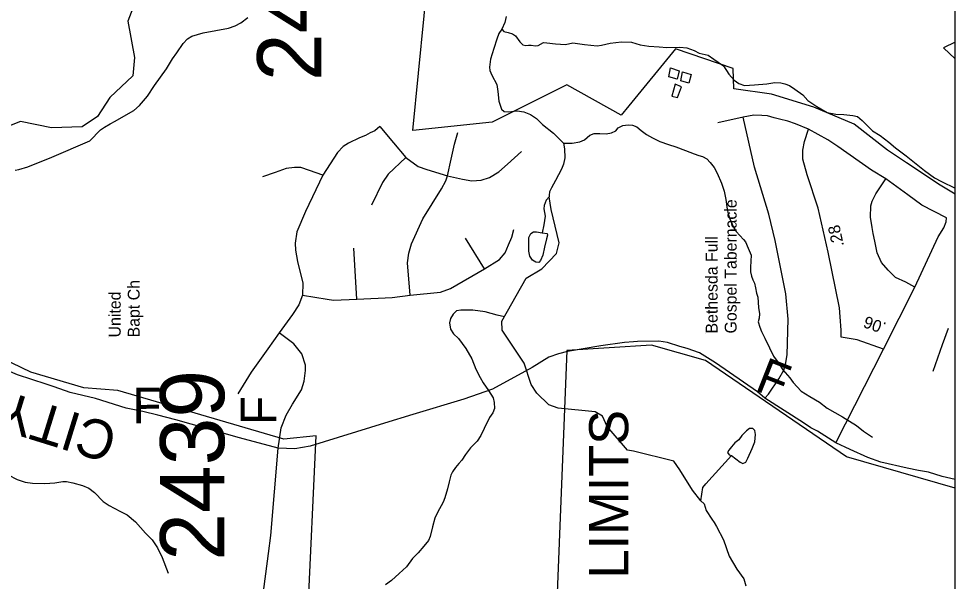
# Model space of a CAD drawing. Extents: x 1372027 to 1374286, y 553832 to 556743.
# Drawn here: x 1373346.9 to 1373483.1, y 554175.4 to 554256.9 of the extents above; entities that cross this region are included whole.
import ezdxf

# ---------------------------------------------------------------- set-up
doc = ezdxf.new("R2010")
doc.units = 0
for name, color, linetype in [('Old_Level_12', 7, 'Continuous'), ('Prop Dimension', 7, 'Continuous'), ('Prop Dimension Text', 7, 'Continuous'), ('Prop Guardrail', 7, 'Continuous'), ('Prop Paved Shoulder', 7, 'Continuous'), ('Sheet Clip Boundary CELL', 7, 'Continuous'), ('Sheet North Arrow Point CELL', 7, 'Continuous'), ('Sheet Sticker Preliminary CELL', 7, 'Continuous')]:
    doc.layers.add(name, color=color, linetype=linetype)

msp = doc.modelspace()

# ---------------------------------------------------------------- linework, layer by layer
at = {"layer": 'Prop Dimension'}
for points in [[(1373390.4, 554295.52), (1373383.17, 554280.73), (1373382.39, 554279.36), (1373381.04, 554279.17), (1373379.07, 554280.34), (1373376.02, 554281.86), (1373374.59, 554280.87), (1373372.97, 554278.37), (1373369.48, 554270.06), (1373367.31, 554268.19), (1373366.41, 554268.21), (1373364.1, 554266.68), (1373363.6, 554265.63), (1373363.97, 554260.02), (1373362.66, 554256.56), (1373363.65, 554251.29), (1373363.4, 554248.66), (1373360.07, 554245.52), (1373358.27, 554242.76), (1373356.06, 554241.27), (1373351.62, 554241.09), (1373347.13, 554242), (1373341.46, 554239.82)], [(1373417.56, 554257.23), (1373417.34, 554256.39), (1373416.94, 554255.43)], [(1373416.94, 554255.43), (1373416.49, 554254.81), (1373416.18, 554253.98), (1373415.78, 554252.6), (1373415.28, 554251.05), (1373415.14, 554249.88), (1373415.16, 554249.42), (1373415.49, 554248.74), (1373416.17, 554247.38), (1373416.36, 554246.37), (1373416.5, 554244.98), (1373416.7, 554244.26), (1373416.89, 554243.79), (1373417.26, 554243.45), (1373417.87, 554243.44), (1373419.16, 554243.58), (1373420.12, 554243.43), (1373421.08, 554243.03), (1373421.95, 554242.47), (1373422.83, 554241.61), (1373424.39, 554240.32), (1373425.88, 554238.9)], [(1373425.88, 554238.9), (1373426.03, 554238.06), (1373426.04, 554236.76), (1373425.85, 554235.83), (1373425.59, 554235.12), (1373424.72, 554233.46), (1373424.14, 554232.42), (1373423.84, 554231.8), (1373423.79, 554231.34), (1373423.79, 554231.08)], [(1373445.79, 554187), (1373444.57, 554188.56), (1373442.71, 554191.49), (1373441.87, 554192.75), (1373436, 554194.19), (1373435.16, 554194.37), (1373432.2, 554197.81), (1373431.54, 554199.31), (1373430.46, 554199.91), (1373425.08, 554200.45), (1373423.75, 554200.92), (1373422.01, 554202.6), (1373421.17, 554203.86), (1373420.15, 554206.97), (1373416.98, 554211.76), (1373416.93, 554213.07), (1373420.43, 554219.28), (1373422.73, 554220.65), (1373424.85, 554222.87), (1373425.22, 554224.45), (1373424.08, 554229.26), (1373423.79, 554231.08)], [(1373445.79, 554187), (1373446.25, 554186.58), (1373446.55, 554185.62), (1373447.39, 554184.37), (1373447.69, 554183.89), (1373448.05, 554183.29), (1373449.07, 554181.37), (1373449.9, 554178.98), (1373450.98, 554177.12), (1373452, 554175.68), (1373452.3, 554174.66)]]:
    msp.add_lwpolyline(points, dxfattribs=at)
at = {"layer": 'Prop Dimension Text'}
for points in [[(1373151.67, 554391.53), (1373151.67, 554060.53), (1373482.67, 554060.53), (1373482.67, 554391.53)], [(1373508.08, 554391.53), (1373508.08, 554060.53), (1373482.67, 554060.53), (1373482.67, 554391.53)]]:
    msp.add_lwpolyline(points, close=True, dxfattribs=at)
for points in [[(1373442.11, 554252.57), (1373435.36, 554244.29), (1373434.22, 554242.95), (1373426.33, 554247.36), (1373415.53, 554241.91), (1373404.03, 554240.74), (1373407.28, 554274.04)], [(1373482.67, 554253.55), (1373480.99, 554252.69), (1373482.67, 554251.13)], [(1373482.67, 554231.48), (1373480.47, 554232.77), (1373475.6, 554236.03), (1373472.84, 554237.87), (1373468, 554241.64), (1373462.19, 554244.11), (1373456.04, 554245.97), (1373450.58, 554246.78), (1373450.46, 554249.72), (1373442.11, 554252.57)], [(1373482.67, 554188.86), (1373466.92, 554193.38), (1373446.44, 554207.34), (1373438.62, 554209.57), (1373426.33, 554208.82), (1373424.84, 554171.24), (1373413.67, 554168.63), (1373414.42, 554122.11), (1373405.85, 554116.53), (1373395.43, 554113.92), (1373393.57, 554120.62), (1373386.65, 554120.29), (1373386.48, 554133.33), (1373386.62, 554163.49), (1373388.8, 554170.42), (1373390.01, 554196.42), (1373385.31, 554195.94), (1373361.22, 554203), (1373356.27, 554203.41), (1373348.59, 554205.69), (1373344.52, 554207.63)]]:
    msp.add_lwpolyline(points, dxfattribs=at)
at = {"layer": 'Prop Paved Shoulder'}
for p, q in [((1373451.93, 554242.66), (1373448.24, 554241.85)), ((1373414.42, 554220.65), (1373411.64, 554225.08)), ((1373395.9, 554216.25), (1373395.46, 554223.65)), ((1373472.25, 554209.02), (1373476.8, 554217.99)), ((1373465.36, 554195.41), (1373472.25, 554209.02))]:
    msp.add_line(p, q, dxfattribs=at)
for points in [[(1373346.34, 554234.97), (1373346.89, 554235.04), (1373348.19, 554235.46), (1373351.66, 554236.86), (1373357.14, 554239.21), (1373358.73, 554240.8), (1373359.28, 554241.21), (1373360.09, 554241.7), (1373360.86, 554242.06), (1373362.43, 554242.99), (1373363.55, 554243.61), (1373364.37, 554244.32), (1373365.51, 554245.69), (1373366.55, 554247.24), (1373368.28, 554249.68), (1373369.15, 554251.09), (1373369.8, 554252), (1373370.69, 554253.35), (1373371.33, 554254), (1373371.96, 554254.39), (1373373.6, 554254.88), (1373377.28, 554255.55), (1373378.23, 554255.91), (1373379.08, 554256.33), (1373380.1, 554257.11)], [(1373461.41, 554240.89), (1373459.52, 554241.67), (1373458.41, 554242.06), (1373457.18, 554242.35), (1373456.42, 554242.55), (1373455.47, 554242.84), (1373454.65, 554242.91), (1373453.48, 554242.92), (1373451.93, 554242.66)], [(1373455.06, 554201.88), (1373455.6, 554202.47), (1373457.11, 554204.72), (1373457.81, 554205.95), (1373458.06, 554206.77), (1373458.28, 554208.17), (1373458.44, 554213.37), (1373458.13, 554217.02), (1373456.55, 554224.76), (1373455.66, 554228.58), (1373453.54, 554235.38), (1373451.93, 554242.66)], [(1373399.22, 554241.29), (1373398.49, 554240.67), (1373397.83, 554240.36), (1373397.16, 554239.97), (1373396.28, 554239.65), (1373394.67, 554238.86), (1373393.91, 554238.41), (1373393.09, 554237.53), (1373390.97, 554234.24)], [(1373399.22, 554241.29), (1373401.21, 554238.91), (1373403.01, 554236.81)], [(1373409.05, 554234.16), (1373409.58, 554236.54), (1373410.06, 554238.75), (1373410.53, 554240.45)], [(1373466.15, 554210.73), (1373466.12, 554211.74), (1373466.01, 554213.68), (1373465.87, 554215), (1373464.23, 554223.09), (1373462.8, 554229.46), (1373461.19, 554234.3), (1373460.59, 554236.58), (1373460.56, 554237.85), (1373460.81, 554239.13), (1373461.41, 554240.89)], [(1373472.63, 554233.73), (1373470.51, 554234.95), (1373465.66, 554238.41), (1373464.21, 554239.37), (1373461.41, 554240.89)], [(1373409.05, 554234.16), (1373411.2, 554233.67), (1373412.55, 554233.44), (1373413.94, 554233.5), (1373415.11, 554233.9), (1373416.47, 554234.73), (1373417.74, 554235.83), (1373419.76, 554237.69)], [(1373403.01, 554236.81), (1373400.42, 554234.4), (1373399.6, 554233.16), (1373398.02, 554229.9)], [(1373403.01, 554236.81), (1373404.78, 554235.51), (1373406.04, 554235.05), (1373409.05, 554234.16)], [(1373390.97, 554234.24), (1373389.04, 554234.94), (1373387.78, 554235.36), (1373386.86, 554235.36), (1373385.66, 554235.23), (1373384.05, 554234.61), (1373382.22, 554233.98)], [(1373390.97, 554234.24), (1373388.44, 554228.96), (1373387.18, 554226.03), (1373386.93, 554224.4), (1373386.99, 554223.35), (1373387.3, 554221.73), (1373388.06, 554218.6), (1373388, 554216.84)], [(1373403.61, 554216.84), (1373403.26, 554221.51), (1373403.42, 554222.91), (1373403.8, 554224.28), (1373405.44, 554227.9), (1373408.19, 554232.27), (1373408.79, 554233.44), (1373409.05, 554234.16)], [(1373476.8, 554217.99), (1373475.51, 554218.71), (1373474.02, 554219.4), (1373472.95, 554220.47), (1373472, 554221.58), (1373471.37, 554222.98), (1373471.02, 554224.67), (1373470.78, 554225.78), (1373470.63, 554226.63), (1373470.39, 554228.16), (1373470.42, 554229.79), (1373470.61, 554230.47), (1373471.15, 554231.55), (1373472.63, 554233.73)], [(1373481.42, 554228.05), (1373477.81, 554229.87), (1373475.82, 554231.37), (1373472.63, 554233.73)], [(1373476.8, 554217.99), (1373480.22, 554225.31), (1373481.04, 554226.61), (1373481.35, 554227.46), (1373481.42, 554228.05)], [(1373414.42, 554220.65), (1373416.57, 554222.03), (1373417.39, 554222.98), (1373417.9, 554224.12), (1373418.37, 554225.26), (1373418.65, 554226.37)], [(1373403.61, 554216.84), (1373408.04, 554217.26), (1373409.46, 554217.78), (1373414.42, 554220.65)], [(1373388, 554216.84), (1373387.46, 554215.45), (1373386.58, 554214.02), (1373384.62, 554211.35)], [(1373388, 554216.84), (1373391.6, 554216.25), (1373392.49, 554216.12), (1373395.9, 554216.25)], [(1373395.9, 554216.25), (1373401.02, 554216.51), (1373403.61, 554216.84)], [(1373384.62, 554211.35), (1373382.97, 554209.07), (1373380.57, 554205.68), (1373378.61, 554202.55)], [(1373384.49, 554194.66), (1373384.93, 554197.6), (1373385.63, 554199.42), (1373386.58, 554201.05), (1373387.85, 554203.1), (1373388.24, 554204.38), (1373388.46, 554205.89), (1373388.46, 554206.67), (1373387.9, 554208.35), (1373386.77, 554209.78), (1373384.62, 554211.35)], [(1373481.65, 554212), (1373480.79, 554209.64), (1373479.44, 554205.78)], [(1373455.06, 554201.88), (1373454, 554202.81), (1373447.91, 554207.01), (1373445.58, 554208.45), (1373443.79, 554209.11), (1373442.75, 554209.39), (1373440.93, 554209.95), (1373439.67, 554210.17), (1373436.6, 554210.11), (1373436.01, 554210.06), (1373434.71, 554209.95), (1373431.26, 554209.49), (1373426.46, 554208.69), (1373425.12, 554208.35), (1373423.74, 554207.86), (1373421.31, 554206.36), (1373415.56, 554203.22), (1373411.42, 554201.75), (1373403.99, 554199.54), (1373399.91, 554198.26), (1373389.13, 554194.94), (1373386.9, 554194.55), (1373384.49, 554194.66)], [(1373472.25, 554209.02), (1373468.46, 554210.38), (1373466.15, 554210.73)], [(1373384.49, 554194.66), (1373378.85, 554196.15), (1373369.62, 554198.76), (1373367.03, 554199.45), (1373364.83, 554199.97), (1373362.43, 554200.47), (1373358.01, 554201.87), (1373354.32, 554202.74), (1373352, 554203.55), (1373350.82, 554203.94), (1373346.68, 554205.28), (1373344.22, 554206.34), (1373342.96, 554207.36)], [(1373465.36, 554195.41), (1373462.7, 554197.12), (1373461.75, 554197.61), (1373460.67, 554198.3), (1373455.06, 554201.88)], [(1373482.67, 554190.09), (1373480.78, 554190.53), (1373478.79, 554191.18), (1373477.37, 554191.41), (1373475.7, 554191.73), (1373471.9, 554192.64), (1373469.98, 554193.3), (1373467.45, 554194.44), (1373465.36, 554195.41)], [(1373381.98, 554170.91), (1373383.1, 554179.35), (1373383.43, 554181.97), (1373384.49, 554194.66)]]:
    msp.add_lwpolyline(points, dxfattribs=at)
at = {"layer": 'Sheet North Arrow Point CELL'}
for p, q in [((1373446.49, 554211.28), (1373446.49, 554211.28)), ((1373359.92, 554210.71), (1373359.92, 554210.71))]:
    msp.add_line(p, q, dxfattribs=at)
at = {"layer": 'Sheet Sticker Preliminary CELL'}
for points in [[(1373416.94, 554255.43), (1373417.22, 554255.09), (1373417.84, 554254.95), (1373418.47, 554254.73), (1373418.88, 554254.47), (1373419.54, 554253.57), (1373419.96, 554253.14), (1373420.4, 554253.05), (1373420.78, 554253.08), (1373421.16, 554253.08), (1373421.8, 554253.02), (1373422.21, 554253.05), (1373422.95, 554253.46), (1373423.44, 554253.41), (1373424.7, 554253.3), (1373426.13, 554253.18), (1373427.22, 554253.41), (1373428.9, 554253.17), (1373430.74, 554253), (1373431.38, 554253.11), (1373432.65, 554253.38), (1373434.29, 554253.56), (1373435.72, 554253.53), (1373436.97, 554253.12), (1373438.22, 554252.97), (1373439.74, 554252.86), (1373440.87, 554252.75), (1373442.72, 554252.8), (1373443.73, 554252.69), (1373444.81, 554252.33), (1373445.52, 554251.94), (1373446.86, 554251.62), (1373447.68, 554251.05), (1373449.06, 554250.1), (1373449.82, 554248.91), (1373450.6, 554248.01), (1373451.31, 554247.53), (1373452.1, 554247.26), (1373453.57, 554247.32), (1373455.34, 554247.49), (1373456.52, 554247.68), (1373457.4, 554247.62), (1373457.98, 554247.48), (1373458.65, 554247.25), (1373459.4, 554246.73), (1373460.57, 554245.87), (1373461.29, 554245.06), (1373462.62, 554244.19), (1373464.08, 554243.32), (1373465.34, 554243.08), (1373466.51, 554243.02), (1373467.81, 554242.9), (1373468.52, 554242.76), (1373469.18, 554242.16), (1373469.8, 554241.52), (1373470.7, 554240.66), (1373471.79, 554240), (1373473.03, 554239.01), (1373474.01, 554238.19), (1373475.55, 554237.03), (1373478.23, 554234.91), (1373479.68, 554233.83), (1373480.68, 554233.31), (1373482.67, 554232.36)], [(1373441.16, 554248.5), (1373441.4, 554249.8), (1373442.65, 554249.39), (1373442.36, 554248.14), (1373441.16, 554248.5)], [(1373442.88, 554247.92), (1373443.14, 554249.21), (1373444.39, 554248.85), (1373444.04, 554247.6), (1373442.88, 554247.92)], [(1373442.06, 554247.43), (1373441.56, 554245.72), (1373442.4, 554245.49), (1373442.98, 554247.07), (1373442.06, 554247.43)], [(1373425.88, 554238.9), (1373427.13, 554238.88), (1373428.24, 554239.06), (1373428.92, 554239.38), (1373429.67, 554240.04), (1373430.31, 554240.28), (1373431.11, 554240.26), (1373432.04, 554240.24), (1373432.8, 554240.4), (1373433.44, 554240.68), (1373433.78, 554241.09), (1373434.49, 554241.45), (1373435.22, 554241.52), (1373435.85, 554241.51), (1373436.52, 554241.24), (1373437.13, 554240.73), (1373437.88, 554240.12), (1373438.75, 554239.64), (1373439.84, 554239.11), (1373441.09, 554238.71), (1373442.17, 554238.35), (1373443.55, 554237.82), (1373444.8, 554237.33), (1373445.47, 554237.11), (1373446, 554236.93), (1373446.63, 554236.62), (1373447.12, 554236.06), (1373447.69, 554235.34), (1373448.17, 554234.53), (1373448.78, 554233.09), (1373449.17, 554231.9), (1373449.41, 554230.72), (1373449.58, 554229.29), (1373449.74, 554228.61), (1373449.97, 554227.9), (1373450.5, 554226.71), (1373450.9, 554226.07), (1373451.44, 554225.47), (1373451.98, 554224.91), (1373452.26, 554224.57), (1373452.66, 554223.64), (1373453.07, 554222.62), (1373452.98, 554220.9), (1373452.97, 554220.23), (1373453.13, 554219.6), (1373453.32, 554219.04), (1373453.57, 554218.57), (1373453.71, 554217.9), (1373453.84, 554217.14), (1373454.03, 554216.55), (1373454.12, 554215.03), (1373454.28, 554214.15), (1373454.26, 554213.48), (1373454.11, 554212.98), (1373454.32, 554212.22), (1373454.6, 554211.58), (1373455.08, 554210.6), (1373455.73, 554209.2), (1373456.32, 554207.97), (1373456.98, 554207.08), (1373457.68, 554206.01), (1373458.71, 554204.85), (1373459.19, 554204.17), (1373460.34, 554202.93), (1373461.58, 554202.15), (1373463, 554201.32), (1373464.12, 554200.46), (1373466.31, 554199.19), (1373468.34, 554197.93), (1373469.37, 554197.11), (1373470.7, 554196.24)], [(1373423.79, 554231.08), (1373423.35, 554230.63), (1373423.04, 554229.84), (1373423.03, 554229.38), (1373423.18, 554228.29), (1373423.02, 554227.03), (1373422.75, 554225.9)], [(1373422.75, 554225.9), (1373423.51, 554225.8), (1373423.54, 554225.55), (1373423.41, 554225), (1373423.09, 554223.79), (1373422.84, 554222.62), (1373422.53, 554221.87), (1373422.29, 554221.58), (1373421.86, 554221.63), (1373421.36, 554221.89), (1373420.96, 554222.49), (1373420.84, 554223.2), (1373420.82, 554224.22), (1373420.84, 554225.18), (1373421.11, 554225.8), (1373421.5, 554226.01), (1373421.95, 554226), (1373422.75, 554225.9)], [(1373417.29, 554213.71), (1373416.24, 554213.93), (1373414.49, 554214.43), (1373412.72, 554214.68), (1373410.96, 554214.67), (1373410.32, 554214.56), (1373409.85, 554214.06), (1373409.46, 554213.44), (1373409.32, 554212.82), (1373409.48, 554211.93), (1373409.91, 554211.21), (1373410.62, 554210.56), (1373411.68, 554209.11), (1373412.58, 554207.58), (1373413.13, 554206.1), (1373413.78, 554204.91), (1373414.23, 554204.1), (1373415, 554203.03), (1373415.65, 554201.97), (1373415.81, 554201.25), (1373415.83, 554200.41), (1373415.61, 554199.78), (1373415.13, 554199.08), (1373414.34, 554197.5), (1373413.86, 554196.5), (1373413.34, 554195.67), (1373412.35, 554194.72), (1373411.66, 554193.73), (1373411.13, 554192.9), (1373410.67, 554192.41), (1373410.19, 554191.83), (1373409.75, 554191.21), (1373409.5, 554190.75), (1373409.27, 554189.75), (1373409.03, 554188.74), (1373408.67, 554187.45), (1373408.4, 554186.82), (1373407.58, 554185.33), (1373407.19, 554184.5), (1373406.87, 554183.24), (1373406.53, 554181.86), (1373406.28, 554181.28), (1373405.62, 554180.45), (1373404.76, 554179.46), (1373403.95, 554178.64), (1373403.08, 554177.44), (1373402.01, 554176.49), (1373400.9, 554175.46), (1373400.05, 554174.85)], [(1373450.23, 554193.56), (1373451.46, 554192.61), (1373451.89, 554192.43), (1373452.31, 554192.63), (1373452.61, 554193.22), (1373453.23, 554194.59), (1373453.59, 554195.55), (1373453.7, 554196.64), (1373453.63, 554197.23), (1373453.3, 554197.49), (1373452.84, 554197.5), (1373452.4, 554197.17), (1373451.71, 554196.47), (1373451.29, 554195.85), (1373450.69, 554195.4), (1373450.22, 554194.86), (1373449.86, 554194.37), (1373449.65, 554194.03), (1373449.9, 554193.69), (1373450.23, 554193.56)], [(1373445.79, 554187), (1373446.07, 554188.92), (1373446.49, 554189.46), (1373450.23, 554193.56)], [(1373344.63, 554191.26), (1373345.33, 554190.78), (1373346.62, 554190.12), (1373347.79, 554189.72), (1373348.83, 554189.57), (1373350.64, 554189.54), (1373352.07, 554189.63), (1373353.25, 554189.82), (1373353.8, 554189.81), (1373354.71, 554189.62), (1373356.1, 554189.25), (1373357.02, 554188.86), (1373357.84, 554188.21), (1373359.12, 554186.92), (1373359.95, 554186.32), (1373360.69, 554185.96), (1373361.61, 554185.48), (1373362.56, 554184.96), (1373363.77, 554183.97), (1373365.25, 554182.34), (1373366.19, 554181.35), (1373367, 554180.21), (1373367.64, 554178.8), (1373368.53, 554176.52)]]:
    msp.add_lwpolyline(points, dxfattribs=at)

# ---------------------------------------------------------------- texts
at = {"layer": 'Old_Level_12'}
for s, p in [('2482', (1373390.74, 554247.88)), ('2439', (1373376.66, 554178.32))]:
    msp.add_text(s, height=9.301, rotation=90, dxfattribs=at).set_placement(p)
at = {"layer": 'Prop Guardrail'}
for s, rotation, p in [('.28', 102.5848, (1373466.55, 554224.03)), ('.06', 160.2006, (1373472.8, 554212.77))]:
    msp.add_text(s, height=1.722, rotation=rotation, dxfattribs=at).set_placement(p)
at = {"layer": 'Sheet Clip Boundary CELL'}
for s, rotation, p in [('CITY', 162.7594, (1373361.5, 554197.85)), ('LIMITS', 90, (1373435.25, 554175.75))]:
    msp.add_text(s, height=5.67, rotation=rotation, dxfattribs=at).set_placement(p)
at = {"layer": 'Sheet North Arrow Point CELL'}
for s, height, rotation, p in [('Gospel Tabernacle', 1.7224, 90, (1373450.97, 554211.28)), ('Bethesda Full', 1.7224, 90, (1373448.21, 554211.28)), ('Bapt Ch', 1.722, 90, (1373364.39, 554210.71)), ('United ', 1.722, 90, (1373361.64, 554210.71)), ('F', 5.17, 338.5023, (1373453.43, 554203.09)), ('F', 5.17, 0.1953, (1373363.36, 554198.25)), ('F', 5.17, 90, (1373384.21, 554198))]:
    msp.add_text(s, height=height, rotation=rotation, dxfattribs=at).set_placement(p)

doc.saveas('drawing.dxf')
